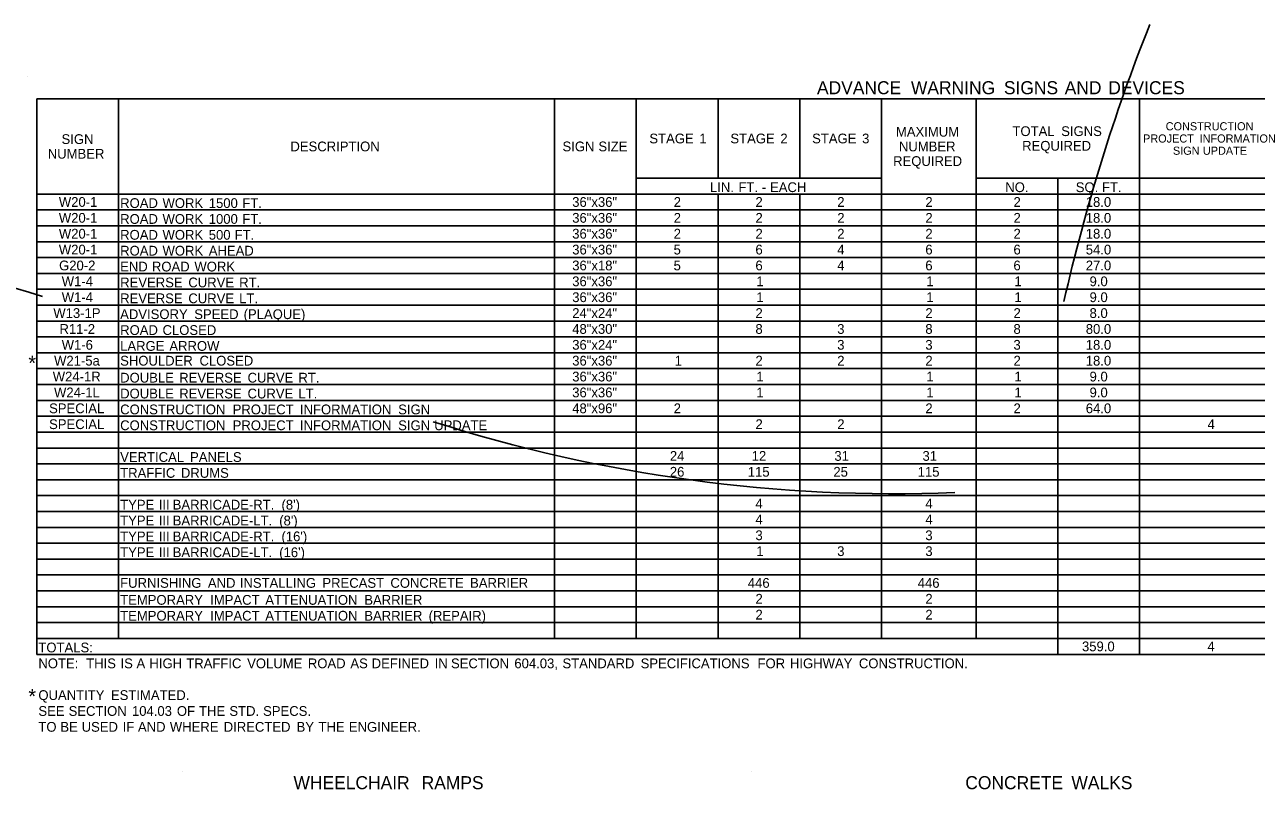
# Model space of a CAD drawing. Extents: x 1197542 to 1207068, y 230488 to 237324.
# Drawn here: x 1198077 to 1198833, y 232230 to 232700 of the extents above; entities that cross this region are included whole.
import ezdxf

# ---------------------------------------------------------------- set-up
doc = ezdxf.new("R2010")
doc.units = 0
doc.layers.add('Default', color=7, linetype='Continuous')
doc.layers.add('R_Proposed Road_Shoulder', color=7, linetype='Continuous')

msp = doc.modelspace()

# ---------------------------------------------------------------- linework, layer by layer
at = {"layer": 'Default'}
for p, q in [((1198078.69, 232668.14), (1198078.69, 232668.14)), ((1198084.54, 232654.49), (1199275.99, 232654.49)), ((1198084.54, 232313.24), (1198084.54, 232654.49)), ((1198084.54, 232313.24), (1198084.54, 232654.49)), ((1198134.75, 232322.99), (1198134.75, 232654.49)), ((1198402.39, 232322.99), (1198402.39, 232654.49)), ((1198452.6, 232322.99), (1198452.6, 232654.49)), ((1198502.81, 232605.74), (1198502.81, 232654.49)), ((1198553.02, 232605.74), (1198553.02, 232654.49)), ((1198603.24, 232322.99), (1198603.24, 232654.49)), ((1198661.25, 232322.99), (1198661.25, 232654.49)), ((1198761.67, 232313.24), (1198761.67, 232654.49)), ((1198452.6, 232605.74), (1198603.24, 232605.74)), ((1198603.24, 232322.99), (1198603.24, 232605.74)), ((1198661.25, 232605.74), (1199275.99, 232605.74)), ((1198711.46, 232313.24), (1198711.46, 232605.74)), ((1198084.54, 232595.99), (1199275.99, 232595.99)), ((1198134.75, 232361.99), (1198134.75, 232595.99)), ((1198402.39, 232322.99), (1198402.39, 232595.99)), ((1198452.6, 232322.99), (1198452.6, 232595.99)), ((1198502.81, 232322.99), (1198502.81, 232595.99)), ((1198502.81, 232322.99), (1198502.81, 232595.99)), ((1198553.02, 232322.99), (1198553.02, 232595.99)), ((1198553.02, 232322.99), (1198553.02, 232595.99)), ((1198603.24, 232595.99), (1199275.99, 232595.99)), ((1198711.46, 232322.99), (1198711.46, 232595.99)), ((1198761.67, 232313.24), (1198761.67, 232595.99)), ((1198084.54, 232586.24), (1199275.99, 232586.24)), ((1198084.54, 232576.49), (1199275.99, 232576.49)), ((1198084.54, 232566.74), (1199275.99, 232566.74)), ((1198084.54, 232556.99), (1199275.99, 232556.99)), ((1198084.54, 232547.24), (1199275.99, 232547.24)), ((1198084.54, 232537.49), (1199275.99, 232537.49)), ((1198084.54, 232527.74), (1199275.99, 232527.74)), ((1198084.54, 232517.99), (1199275.99, 232517.99)), ((1198084.54, 232508.24), (1199275.99, 232508.24)), ((1198084.54, 232498.49), (1199275.99, 232498.49)), ((1198084.54, 232488.74), (1199275.99, 232488.74)), ((1198084.54, 232478.99), (1199275.99, 232478.99)), ((1198084.54, 232469.24), (1199275.99, 232469.24)), ((1198084.54, 232459.49), (1199275.99, 232459.49)), ((1198084.54, 232449.74), (1199275.99, 232449.74)), ((1198084.54, 232439.99), (1199275.99, 232439.99)), ((1198084.54, 232430.24), (1199275.99, 232430.24)), ((1198084.54, 232420.49), (1199275.99, 232420.49)), ((1198084.54, 232410.74), (1199275.99, 232410.74)), ((1198084.54, 232400.99), (1199275.99, 232400.99)), ((1198084.54, 232391.24), (1199275.99, 232391.24)), ((1198084.54, 232381.49), (1199275.99, 232381.49)), ((1198084.54, 232371.74), (1199275.99, 232371.74)), ((1198084.54, 232361.99), (1199275.99, 232361.99)), ((1198084.54, 232352.24), (1198134.75, 232352.24)), ((1198134.75, 232352.24), (1199275.99, 232352.24)), ((1198134.75, 232322.99), (1198134.75, 232352.24)), ((1198084.54, 232342.49), (1199275.99, 232342.49)), ((1198084.54, 232332.74), (1199275.99, 232332.74)), ((1198084.54, 232322.99), (1199275.99, 232322.99)), ((1198084.54, 232313.24), (1199275.99, 232313.24)), ((1198174.22, 232241.22), (1198174.22, 232241.22)), ((1198523.23, 232241.22), (1198523.23, 232241.22))]:
    msp.add_line(p, q, dxfattribs=at)
at = {"layer": 'R_Proposed Road_Shoulder'}
for centre, radius, start, end in [((1199832.91, 232277.25), 1145.92, 158.34711, 167.25666), ((1197804.3, 231647.33), 930, 72.24163, 106.3876), ((1198611.58, 233341.85), 930, 252.24163, 272.25666)]:
    msp.add_arc(centre, radius, start, end, dxfattribs=at)

# ---------------------------------------------------------------- texts
at = {"layer": 'Default'}
for s, height, p in [('ADVANCE', 8, (1198563.57, 232657.32)), (' WARNING', 8, (1198618.29, 232657.32)), (' SIGNS', 8, (1198675.36, 232657.32)), (' AND', 8, (1198712.7, 232657.32)), (' DEVICES', 8, (1198739.47, 232657.32)), ('MAXIMUM', 6, (1198612.05, 232631.24)), ('TOTAL', 6, (1198683.61, 232631.62)), (' SIGNS', 6, (1198711.3, 232631.62)), ('CONSTRUCTION', 5, (1198777.69, 232635.12)), ('SIGN', 6, (1198099.73, 232626.74)), ('DESCRIPTION', 6, (1198240.25, 232622.24)), ('SIGN', 6, (1198407.31, 232622.24)), (' SIZE', 6, (1198427.13, 232622.24)), ('STAGE', 6, (1198460.66, 232627.12)), (' 1', 6, (1198489.12, 232627.12)), ('STAGE', 6, (1198510.4, 232627.12)), (' 2', 6, (1198538.87, 232627.12)), ('STAGE', 6, (1198560.58, 232627.12)), (' 3', 6, (1198589.05, 232627.12)), ('NUMBER', 6, (1198613.87, 232622.24)), ('REQUIRED', 6, (1198689.54, 232622.62)), ('PROJECT', 5, (1198763.79, 232627.62)), (' INFORMATION', 5, (1198796.64, 232627.62)), ('NUMBER', 6, (1198091.27, 232617.74)), ('SIGN', 5, (1198782.13, 232620.12)), (' UPDATE', 5, (1198798.65, 232620.12)), ('REQUIRED', 6, (1198610.32, 232613.24)), ('LIN.', 6, (1198497.88, 232597.19)), (' FT.', 6, (1198513.13, 232597.19)), (' -', 6, (1198527.46, 232597.19)), (' EACH', 6, (1198532.52, 232597.19)), ('NO.', 6, (1198679.19, 232597.19)), ('SQ.', 6, (1198722.47, 232597.19)), (' FT.', 6, (1198736.34, 232597.19)), ('W20-1', 6, (1198098.07, 232588.12)), ('ROAD', 6, (1198135.72, 232587.44)), (' WORK', 6, (1198159.5, 232587.44)), (' 1500', 6, (1198187.89, 232587.44)), (' FT.', 6, (1198208.46, 232587.44)), ('36"x36"', 6, (1198413.29, 232588.12)), ('2', 6, (1198475.6, 232588.12)), ('2', 6, (1198525.81, 232588.12)), ('2', 6, (1198576.02, 232588.12)), ('2', 6, (1198630.13, 232588.12)), ('2', 6, (1198684.25, 232588.12)), ('18.0', 6, (1198728.61, 232588.12)), ('W20-1', 6, (1198098.07, 232578.37)), ('ROAD', 6, (1198135.72, 232577.69)), (' WORK', 6, (1198159.5, 232577.69)), (' 1000', 6, (1198187.89, 232577.69)), (' FT.', 6, (1198208.46, 232577.69)), ('36"x36"', 6, (1198413.29, 232578.37)), ('2', 6, (1198475.6, 232578.37)), ('2', 6, (1198525.81, 232578.37)), ('2', 6, (1198576.02, 232578.37)), ('2', 6, (1198630.13, 232578.37)), ('2', 6, (1198684.25, 232578.37)), ('18.0', 6, (1198728.61, 232578.37)), ('W20-1', 6, (1198098.07, 232568.62)), ('ROAD', 6, (1198135.72, 232567.94)), (' WORK', 6, (1198159.5, 232567.94)), (' 500', 6, (1198187.89, 232567.94)), (' FT.', 6, (1198203.8, 232567.94)), ('36"x36"', 6, (1198413.29, 232568.62)), ('2', 6, (1198475.6, 232568.62)), ('2', 6, (1198525.81, 232568.62)), ('2', 6, (1198576.02, 232568.62)), ('2', 6, (1198630.13, 232568.62)), ('2', 6, (1198684.25, 232568.62)), ('18.0', 6, (1198728.61, 232568.62)), ('W20-1', 6, (1198098.07, 232558.87)), ('ROAD', 6, (1198135.72, 232558.19)), (' WORK', 6, (1198159.5, 232558.19)), (' AHEAD', 6, (1198187.89, 232558.19)), ('36"x36"', 6, (1198413.29, 232558.87)), ('5', 6, (1198475.54, 232558.87)), ('6', 6, (1198525.78, 232558.87)), ('4', 6, (1198576, 232558.87)), ('6', 6, (1198630.1, 232558.87)), ('6', 6, (1198684.21, 232558.87)), ('54.0', 6, (1198728.61, 232558.87)), ('G20-2', 6, (1198098.22, 232549.12)), ('END', 6, (1198135.72, 232548.44)), (' ROAD', 6, (1198152.98, 232548.44)), (' WORK', 6, (1198179.08, 232548.44)), ('36"x18"', 6, (1198413.29, 232549.12)), ('5', 6, (1198475.54, 232549.12)), ('6', 6, (1198525.78, 232549.12)), ('4', 6, (1198576, 232549.12)), ('6', 6, (1198630.1, 232549.12)), ('6', 6, (1198684.21, 232549.12)), ('27.0', 6, (1198728.61, 232549.12)), ('W1-4', 6, (1198099.84, 232539.37)), ('REVERSE', 6, (1198135.72, 232538.69)), (' CURVE', 6, (1198175.35, 232538.69)), (' RT.', 6, (1198206.58, 232538.69)), ('36"x36"', 6, (1198413.29, 232539.37)), ('1', 6, (1198526.36, 232539.37)), ('1', 6, (1198630.68, 232539.37)), ('1', 6, (1198684.8, 232539.37)), ('9.0', 6, (1198730.94, 232539.37)), ('W1-4', 6, (1198099.84, 232529.62)), ('REVERSE', 6, (1198135.72, 232528.94)), (' CURVE', 6, (1198175.35, 232528.94)), (' LT.', 6, (1198206.58, 232528.94)), ('36"x36"', 6, (1198413.29, 232529.62)), ('1', 6, (1198526.36, 232529.62)), ('1', 6, (1198630.68, 232529.62)), ('1', 6, (1198684.8, 232529.62)), ('9.0', 6, (1198730.94, 232529.62)), ('W13-1P', 6, (1198094.69, 232519.87)), ('ADVISORY', 6, (1198135.72, 232519.19)), (' SPEED', 6, (1198178.99, 232519.19)), (' (PLAQUE)', 6, (1198209.3, 232519.19)), ('24"x24"', 6, (1198413.29, 232519.87)), ('2', 6, (1198525.81, 232519.87)), ('2', 6, (1198630.13, 232519.87)), ('2', 6, (1198684.25, 232519.87)), ('8.0', 6, (1198730.94, 232519.87)), ('R11-2', 6, (1198098.45, 232510.12)), ('ROAD', 6, (1198135.72, 232509.44)), (' CLOSED', 6, (1198159.5, 232509.44)), ('48"x30"', 6, (1198413.29, 232510.12)), ('8', 6, (1198525.77, 232510.12)), ('3', 6, (1198575.99, 232510.12)), ('8', 6, (1198630.1, 232510.12)), ('8', 6, (1198684.21, 232510.12)), ('80.0', 6, (1198728.61, 232510.12)), ('W1-6', 6, (1198099.82, 232500.37)), ('LARGE', 6, (1198135.72, 232499.69)), (' ARROW', 6, (1198163.7, 232499.69)), ('36"x24"', 6, (1198413.29, 232500.37)), ('3', 6, (1198575.99, 232500.37)), ('3', 6, (1198630.1, 232500.37)), ('3', 6, (1198684.21, 232500.37)), ('18.0', 6, (1198728.61, 232500.37)), ('*', 9, (1198079.39, 232487.69)), ('W21-5a', 6, (1198095.15, 232490.62)), ('SHOULDER', 6, (1198135.72, 232490.62)), (' CLOSED', 6, (1198182.2, 232490.62)), ('36"x36"', 6, (1198413.29, 232490.62)), ('1', 6, (1198476.15, 232490.62)), ('2', 6, (1198525.81, 232490.62)), ('2', 6, (1198576.02, 232490.62)), ('2', 6, (1198630.13, 232490.62)), ('2', 6, (1198684.25, 232490.62)), ('18.0', 6, (1198728.61, 232490.62)), ('W24-1R', 6, (1198094.33, 232480.87)), ('DOUBLE', 6, (1198135.72, 232480.19)), (' REVERSE', 6, (1198169.75, 232480.19)), (' CURVE', 6, (1198211.71, 232480.19)), (' RT.', 6, (1198242.94, 232480.19)), ('36"x36"', 6, (1198413.29, 232480.87)), ('1', 6, (1198526.36, 232480.87)), ('1', 6, (1198630.68, 232480.87)), ('1', 6, (1198684.8, 232480.87)), ('9.0', 6, (1198730.94, 232480.87)), ('W24-1L', 6, (1198095.12, 232471.12)), ('DOUBLE', 6, (1198135.72, 232470.44)), (' REVERSE', 6, (1198169.75, 232470.44)), (' CURVE', 6, (1198211.71, 232470.44)), ('36"x36"', 6, (1198413.29, 232471.12)), ('1', 6, (1198526.36, 232471.12)), ('1', 6, (1198630.68, 232471.12)), ('1', 6, (1198684.8, 232471.12)), ('9.0', 6, (1198730.94, 232471.12)), (' LT.', 6, (1198242.94, 232470.44)), ('SPECIAL', 6, (1198092.08, 232461.37)), ('CONSTRUCTION', 6, (1198135.72, 232460.69)), (' PROJECT', 6, (1198202.57, 232460.69)), (' INFORMATION', 6, (1198243.87, 232460.69)), (' SIGN', 6, (1198304.19, 232460.69)), ('48"x96"', 6, (1198413.29, 232461.37)), ('2', 6, (1198475.6, 232461.37)), ('2', 6, (1198630.13, 232461.37)), ('2', 6, (1198684.25, 232461.37)), ('64.0', 6, (1198728.61, 232461.37)), ('SPECIAL', 6, (1198092.08, 232451.62)), ('CONSTRUCTION', 6, (1198135.72, 232450.94)), (' PROJECT', 6, (1198202.57, 232450.94)), (' INFORMATION', 6, (1198243.87, 232450.94)), (' SIGN', 6, (1198304.19, 232450.94)), (' UPDATE', 6, (1198326.33, 232450.94)), ('2', 6, (1198525.81, 232451.62)), ('2', 6, (1198576.02, 232451.62)), ('4', 6, (1198803.42, 232451.62)), ('VERTICAL', 6, (1198135.72, 232431.44)), (' PANELS', 6, (1198176.42, 232431.44)), ('24', 6, (1198473.25, 232432.12)), ('12', 6, (1198523.48, 232432.12)), ('31', 6, (1198574.24, 232432.12)), ('31', 6, (1198628.35, 232432.12)), ('TRAFFIC', 6, (1198135.72, 232421.69)), (' DRUMS', 6, (1198170.79, 232421.69)), ('26', 6, (1198473.23, 232422.37)), ('115', 6, (1198521.09, 232422.37)), ('25', 6, (1198573.64, 232422.37)), ('115', 6, (1198625.42, 232422.37)), (" (8')", 6, (1198232.55, 232402.19)), ('4', 6, (1198525.79, 232402.87)), ('4', 6, (1198630.12, 232402.87)), ('TYPE', 6, (1198135.72, 232402.19)), (' III', 6, (1198157.18, 232402.19)), (' BARRICADE-RT.', 6, (1198165.74, 232402.19)), ('TYPE', 6, (1198135.72, 232392.44)), (' III', 6, (1198157.18, 232392.44)), (' BARRICADE-LT.', 6, (1198165.74, 232392.44)), (" (8')", 6, (1198231.15, 232392.44)), ('4', 6, (1198525.79, 232393.12)), ('4', 6, (1198630.12, 232393.12)), ('TYPE', 6, (1198135.72, 232382.69)), (' III', 6, (1198157.18, 232382.69)), (' BARRICADE-RT.', 6, (1198165.74, 232382.69)), (" (16')", 6, (1198232.55, 232382.69)), ('3', 6, (1198525.78, 232383.37)), ('3', 6, (1198630.1, 232383.37)), ('TYPE', 6, (1198135.72, 232372.94)), (' III', 6, (1198157.18, 232372.94)), (' BARRICADE-LT.', 6, (1198165.74, 232372.94)), (" (16')", 6, (1198231.15, 232372.94)), ('1', 6, (1198526.36, 232373.62)), ('3', 6, (1198575.99, 232373.62)), ('3', 6, (1198630.1, 232373.62)), ('FURNISHING', 6, (1198135.72, 232354.12)), (' AND', 6, (1198187.36, 232354.12)), (' INSTALLING', 6, (1198206.95, 232354.12)), (' PRECAST', 6, (1198257.66, 232354.12)), (' CONCRETE', 6, (1198299.42, 232354.12)), (' BARRIER', 6, (1198348.35, 232354.12)), ('446', 6, (1198521.12, 232354.12)), ('446', 6, (1198625.44, 232354.12)), ('TEMPORARY', 6, (1198135.72, 232343.69)), (' IMPACT', 6, (1198188.77, 232343.69)), (' ATTENUATION', 6, (1198222.6, 232343.69)), (' BARRIER', 6, (1198283.4, 232343.69)), ('2', 6, (1198525.81, 232344.37)), ('2', 6, (1198630.13, 232344.37)), ('2', 6, (1198525.81, 232334.62)), ('2', 6, (1198630.13, 232334.62)), ('TEMPORARY', 6, (1198135.72, 232333.94)), (' IMPACT', 6, (1198188.77, 232333.94)), (' ATTENUATION', 6, (1198222.6, 232333.94)), (' BARRIER', 6, (1198283.4, 232333.94)), (' (REPAIR)', 6, (1198322.89, 232333.94)), ('TOTALS:', 6, (1198085.51, 232314.44)), ('359.0', 6, (1198726.29, 232315.12)), ('4', 6, (1198803.31, 232315.12)), ('NOTE:', 6, (1198085.51, 232304.69)), ('  THIS', 6, (1198110.4, 232304.69)), (' IS', 6, (1198133.71, 232304.69)), (' A', 6, (1198143.52, 232304.69)), (' HIGH', 6, (1198151.46, 232304.69)), (' TRAFFIC', 6, (1198174.07, 232304.69)), (' VOLUME', 6, (1198211.46, 232304.69)), (' ROAD', 6, (1198248.74, 232304.69)), (' AS', 6, (1198274.84, 232304.69)), (' DEFINED', 6, (1198287.92, 232304.69)), (' IN', 6, (1198326.6, 232304.69)), (' SECTION', 6, (1198336.62, 232304.69)), (' 604.03,', 6, (1198375.53, 232304.69)), (' STANDARD', 6, (1198405.07, 232304.69)), (' SPECIFICATIONS', 6, (1198453.07, 232304.69)), (' FOR', 6, (1198524.84, 232304.69)), (' HIGHWAY', 6, (1198544.75, 232304.69)), (' CONSTRUCTION.', 6, (1198587.07, 232304.69)), ('*', 9, (1198079.39, 232282.94)), ('QUANTITY', 6, (1198085.51, 232285.19)), (' ESTIMATED.', 6, (1198127.84, 232285.19)), ('SEE', 6, (1198085.51, 232275.44)), (' SECTION', 6, (1198101.84, 232275.44)), (' 104.03', 6, (1198140.75, 232275.44)), (' OF', 6, (1198168.33, 232275.44)), (' THE', 6, (1198181.91, 232275.44)), (' STD.', 6, (1198200.56, 232275.44)), (' SPECS.', 6, (1198221.26, 232275.44)), ('TO', 6, (1198085.51, 232265.69)), (' BE', 6, (1198096.78, 232265.69)), (' USED', 6, (1198109.84, 232265.69)), (' IF', 6, (1198135.02, 232265.69)), (' AND', 6, (1198144.41, 232265.69)), (' WHERE', 6, (1198164, 232265.69)), (' DIRECTED', 6, (1198197.08, 232265.69)), (' BY', 6, (1198241.82, 232265.69)), (' THE', 6, (1198255.27, 232265.69)), (' ENGINEER.', 6, (1198273.92, 232265.69)), ('WHEELCHAIR', 8, (1198242.14, 232230.4)), (' RAMPS', 8, (1198317.85, 232230.4)), ('CONCRETE', 8, (1198654.64, 232230.4)), (' WALKS', 8, (1198716.82, 232230.4))]:
    msp.add_text(s, height=height, dxfattribs=at).set_placement(p)

doc.saveas('drawing.dxf')
